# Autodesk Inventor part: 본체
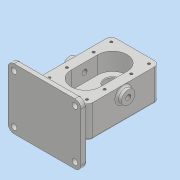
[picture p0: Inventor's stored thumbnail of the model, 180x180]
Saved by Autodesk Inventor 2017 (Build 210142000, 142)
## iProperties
Part Number: 본체
Material: 일반
Document SubType Name: Modeling
Designer: MRC
Mass: 544.668 g
Surface Area: 822.994 cm^2
Volume: 544.668 cm^3
Density: 1 g/cm^3
Appearance: 기본값
Author: MRC
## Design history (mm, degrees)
sketch "스케치1"
  geometry: L1 (-40, -60)-(40, -60); L2 (40, -60)-(40, 60); L3 (40, 60)-(-40, 60); L4 (-40, 60)-(-40, -60); 3 further points
  constraints: 8 end point, 2 midpoint, 2 parallel, 1 horizontal, 1 horizontal alignment, 1 perpendicular, 1 vertical alignment
  dimensions: "d0" = 80 distance of L3.end L2.end; "d1" = 120 distance of L2.end L1.end
extrude "돌출1" new body sketch "스케치1" distance "d2" = 14; taper "d3" = 0 deg; dims "d5" = 39, "d6" = 0
fillet "모깎기1" dims "d4" = 9
sketch "스케치2"
  geometry: L1 (0, -22)-(0, 22); L2 (-24, -22)-(-24, 22); L3 (24, 22)-(24, -22); A1 r 24 centre (0, -22) between (-24, -22) and (24, -22); A2 r 24 centre (0, 22) between (24, 22) and (-24, 22); 2 further points
  constraints: 8 end point, 4 point on circle, 4 tangent, 2 centre point, 1 coincident, 1 midpoint, 1 parallel, 1 vertical
  dimensions: "d7" = 24 radius of A2; "d8" = 44 distance of L1.start L1.end
extrude "돌출2" cut sketch "스케치2" distance "d9" = 29; taper "d10" = 0 deg
sketch "스케치4"
  geometry: C1 r 19 at (0, 22); 1 further point
  constraints: 1 centre point, 1 vertical alignment
  dimensions: "d11" = 38 diameter of C1; "d12" = 22 distance of point (0, 0) C1.centre
extrude "돌출3" join sketch "스케치4" distance "d13" = 17; taper "d14" = 0 deg
sketch "스케치5"
  geometry: C1 r 12.5 at (0, 22); A1 r 24 centre (0, 22) between (24, 22) and (-24, 22) reference; 1 further point
  constraints: 1 centre point, 1 coincident
  dimensions: "d15" = 25 diameter of C1
extrude "돌출4" cut sketch "스케치5" distance "d16" = 15; taper "d17" = 0 deg
sketch "스케치6"
  geometry: C1 r 12.5 at (0, 0) reference; C2 r 8.5 at (0, 0); 1 further point
  constraints: 1 centre point, 1 coincident
  dimensions: "d18" = 17 diameter of C2
extrude "돌출5" cut sketch "스케치6" stored distance "d19" = 15; taper "d20" = 0 deg
sketch "스케치7"
  geometry: C1 r 8.5 at (0, 0) reference; C2 r 19 at (0, 0) reference; C3 r 14 at (0, 0); 1 further point
  constraints: 1 centre point, 1 coincident
  dimensions: "d21" = 28 diameter of C3
extrude "돌출6" cut sketch "스케치7" distance "d22" = 7.3; taper "d23" = 0 deg
sketch "스케치8"
  geometry: C1 r 12.5 at (0, -22); A1 r 24 centre (0, -22) between (-24, -22) and (24, -22) reference; 1 further point
  constraints: 1 centre point, 1 coincident
  dimensions: "d24" = 25 diameter of C1
extrude "돌출7" cut sketch "스케치8" distance "d25" = 15; taper "d26" = 0 deg
sketch "스케치9"
  geometry: A1 r 24 centre (0, 22) between (24, 22) and (-24, 22) reference; 9 further points
  constraints: 6 vertical alignment, 3 horizontal alignment
  dimensions: "d27" = 62 distance of point (31, 51) point (-31, 51); "d28" = 29 distance of point (-31, 51) point (-31, 22); "d29" = 44 distance of point (-31, -22) point (-31, 22); "d30" = 29 distance of point (-31, -51) point (-31, -22); "d31" = 22 vertical distance of point (0, 0) point (-31, -22); "d32" = 31 horizontal distance of A1.centre point (-31, 51); "d33" = 29 distance of point (31, 51) point (31, 22)
hole "구멍1" sketch "스케치9" at (-31, 51), (-31, 22), (-31, -22), (-31, -51), (31, -51), (31, -22), (31, 22), (31, 51) diameter "d34" = 4.134; stored, may be unused: countersink angle "d38" = 90 deg, drill point angle "d40" = 118 deg; dims "d35" = 10, "d36" = 4, "d37" = 2, "d39" = 12
sketch "스케치10"
  geometry: L1 (-90, 44)-(-80, 44); L2 (-80, 44)-(-80, -56); L3 (-80, -56)-(-90, -56); L4 (-90, -56)-(-90, 44); L5 (36, -56)-(8, -56) reference; L6 (-46, 14)-(-46, -15) reference; L7 (-46, -15)-(-34.5, -15) reference; L8 (-34.5, -15)-(-34.5, -30) reference; L9 (-34.5, -30)-(-9.5, -30) reference; L10 (-9.5, -30)-(-9.5, -15) reference; L11 (-9.5, -15)-(9.5, -15) reference; L12 (9.5, -15)-(9.5, -30) reference; L13 (9.5, -30)-(13.5, -30) reference; L14 (13.5, -30)-(13.5, -48.7) reference; L15 (13.5, -48.7)-(8, -48.7) reference; L16 (8, -48.7)-(8, -56) reference; L17 (8, -56)-(3, -56) reference; L18 (3, -56)-(3, -39) reference; L19 (3, -39)-(-60, -39) reference; L20 (-60, -39)-(-60, 14) reference; L21 (-60, 14)-(-46, 14) reference; L22 (46, -15)-(46, 14) reference; L23 (46, 14)-(60, 14) reference; L24 (60, 14)-(60, -39) reference; L25 (60, -39)-(41, -39) reference; L26 (41, -39)-(41, -56) reference; L27 (41, -56)-(36, -56) reference; L28 (36, -56)-(36, -48.7) reference; L29 (36, -48.7)-(30.5, -48.7) reference; L30 (30.5, -48.7)-(30.5, -30) reference; L31 (30.5, -30)-(34.5, -30) reference; L32 (34.5, -30)-(34.5, -15) reference; L33 (34.5, -15)-(46, -15) reference; 1 further point
  constraints: 8 end point, 2 parallel, 1 horizontal, 1 perpendicular, 1 point on line
  dimensions: "d41" = 10 distance of L2.end L3.end; "d42" = 90 distance from line of point (0, 0) L4; "d43" = 100 distance of L3.end L1.start
extrude "돌출8" join sketch "스케치10" stored distance "d44" = 120; taper "d45" = 0 deg
sketch "스케치11"
  geometry: L1 (-80, 44)-(-80, -56) reference; L2 (-80, -39)-(-60, -27.453); L3 (-80, 14)-(-60, 2.453); L4 (-80, -56)-(-90, -56) reference; L5 (-46, 14)-(-46, -15) reference; L6 (-46, -15)-(-34.5, -15) reference; L7 (-34.5, -15)-(-34.5, -30) reference; L8 (-34.5, -30)-(-9.5, -30) reference; L9 (-9.5, -30)-(-9.5, -15) reference; L10 (-9.5, -15)-(9.5, -15) reference; L11 (9.5, -15)-(9.5, -30) reference; L12 (9.5, -30)-(13.5, -30) reference; L13 (13.5, -30)-(13.5, -48.7) reference; L14 (13.5, -48.7)-(8, -48.7) reference; L15 (8, -48.7)-(8, -56) reference; L16 (8, -56)-(3, -56) reference; L17 (3, -56)-(3, -39) reference; L18 (3, -39)-(-60, -39) reference; L19 (-60, -39)-(-60, 14) reference; L20 (-60, 14)-(-46, 14) reference; L21 (46, -15)-(46, 14) reference; L22 (46, 14)-(60, 14) reference; L23 (60, 14)-(60, -39) reference; L24 (60, -39)-(41, -39) reference; L25 (41, -39)-(41, -56) reference; L26 (41, -56)-(36, -56) reference; L27 (36, -56)-(36, -48.7) reference; L28 (36, -48.7)-(30.5, -48.7) reference; L29 (30.5, -48.7)-(30.5, -30) reference; L30 (30.5, -30)-(34.5, -30) reference; L31 (34.5, -30)-(34.5, -15) reference; L32 (34.5, -15)-(46, -15) reference; L33 (-80, 44)-(-80, -56) reference; L34 (-80, -56)-(-90, -56) reference; L35 (-90, -56)-(-90, 44) reference; L36 (-90, 44)-(-80, 44) reference; L37 (-80, 14)-(-80, -39); L38 (-60, -27.453)-(-60, 2.453); 1 further point
  constraints: 8 end point, 4 point on line, 2 collinear
  dimensions: "d46" = 53 distance of L2.start L3.start; "d47" = 17 distance from line of L4 L2.start; "d48" = 60 deg angle of L1 L2; "d49" = 60 deg angle of L1 L3
extrude "돌출9" join sketch "스케치11" stored distance "d50" = 48; taper "d51" = 0 deg
fillet "모깎기2" dims "d52" = 10
sketch "스케치12"
  geometry: C1 r 4.5 at (100, -10); C2 r 4.5 at (100, -90); C3 r 4.5 at (0, -90); C4 r 4.5 at (0, -10); A1 r 10 centre (100, -10) between (110, -10) and (100, 0) reference; A2 r 10 centre (0, -10) between (0, 0) and (-10, -10) reference; A3 r 10 centre (0, -90) between (-10, -90) and (0, -100) reference; A4 r 10 centre (100, -90) between (100, -100) and (110, -90) reference; 1 further point
  constraints: 4 centre point, 4 coincident
  dimensions: "d53" = 9 diameter of C1; "d54" = 9 diameter of C2; "d55" = 9 diameter of C3; "d56" = 9 diameter of C4
extrude "돌출10" cut sketch "스케치12" stored distance "d57" = 48; taper "d58" = 0 deg
sketch "스케치13"
  geometry: C1 r 11 at (-39, 51); 1 further point
  constraints: 1 centre point, 1 coincident
  dimensions: "d59" = 22 diameter of C1
extrude "돌출11" join sketch "스케치13" distance "d60" = 8; taper "d61" = 0 deg
sketch "스케치14"
  geometry: C1 r 11 at (0, 0) reference; 1 further point
  constraints: 1 coincident
hole "구멍2" sketch "스케치14" at (0, 0) diameter "d62" = 8.376; stored, may be unused: countersink angle "d66" = 90 deg, drill point angle "d68" = 118 deg; dims "d63" = 30, "d64" = 4, "d65" = 2, "d67" = 27.3
fillet "모깎기3" dims "d69" = 3
fillet "모깎기4" dims "d70" = 3
chamfer "모따기1" distance "d71" = 1; stored, may be unused: second distance "d72" = 2, angle "d73" = 45 deg
chamfer "모따기2" distance "d74" = 0.7; stored, may be unused: second distance "d75" = 2, angle "d76" = 30 deg
fillet "모깎기5" dims "d77" = 0.5
sketch "스케치15"
  geometry: L1 (0, -3)-(100, -3) reference; L2 (-10, 87)-(-10, 7) reference; 2 further points
  constraints: 1 other
  dimensions: "d78" = 10 distance from line of L1 point (50, 7); "d82" = 60 distance from line of L2 point (50, 7)
feature "엠보싱1" sketch "스케치15" dims "d0" = 80, "d1" = 120, "d79" = 0.5, "d80" = 0
fillet "모깎기6" dims "d81" = 3
node "솔리드1"
mirror "미러1"
node "절단 모서리 투영1"
node "절단 모서리 투영2"
